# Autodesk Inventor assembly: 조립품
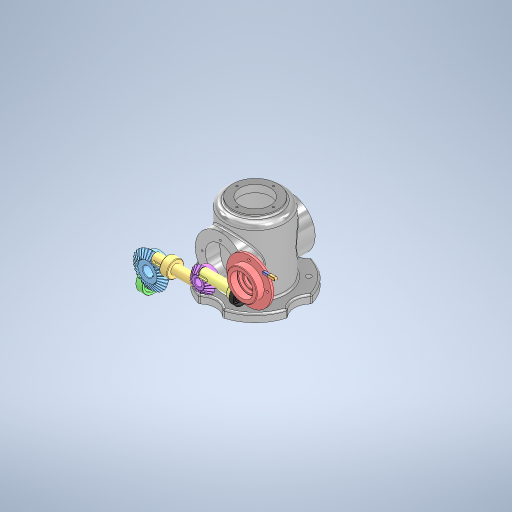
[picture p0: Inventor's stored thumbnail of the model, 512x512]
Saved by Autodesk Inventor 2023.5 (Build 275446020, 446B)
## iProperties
Created: 2026-07
Part Number: 조립품
Document SubType Name: Assembly
Designer: mirae
Author: mirae
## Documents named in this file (12)
- C:\Users\mirae\Desktop\760703V1006\조립품.iam
- C:\Users\mirae\Desktop\760703V1006\본체.ipt
- C:\Users\mirae\Desktop\760703V1006\6각 구멍붙이 볼트 M4x10\6각 구멍붙이 볼트 M4x10.ipt
- C:\Users\mirae\Desktop\760703V1006\깊은 홈 볼 베어링 6203\깊은 홈 볼 베어링 6203.ipt
- C:\Users\mirae\Desktop\760703V1006\메인 베벨기어\메인 베벨기어.ipt
- C:\Users\mirae\Desktop\760703V1006\메인 축\메인 축.ipt
- C:\Users\mirae\Desktop\760703V1006\서브 베벨기어\서브 베벨기어.ipt
- C:\Users\mirae\Desktop\760703V1006\서브 축\서브 축.ipt
- C:\Users\mirae\Desktop\760703V1006\오일 실 17 32 8\오일 실 17 32 8.ipt
- C:\Users\mirae\Desktop\760703V1006\커버\커버.ipt
- C:\Users\mirae\Desktop\760703V1006\평행 키 4x4x14\평행 키 4x4x14.ipt
- C:\Users\mirae\Desktop\760703V1006\평행 키 5x5x14\평행 키 5x5x14.ipt
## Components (1 placed, 1 different names)
1. 6각 구멍붙이 볼트 M4x10:1
